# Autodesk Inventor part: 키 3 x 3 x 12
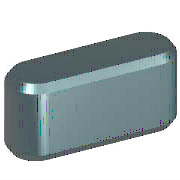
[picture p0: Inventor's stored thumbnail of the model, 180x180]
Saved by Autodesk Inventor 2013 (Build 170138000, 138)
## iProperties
Created: 2012-02
Part Number: 키 3 x 3 x 12
Material: 강철, 연강
Description: 키 및 해당 키홈
Document SubType Name: Modeling
Standard: KS B 1311
Designer: mduedu
Standards Organization: KS
Language: ko-KR
Size Designation: 3 x 3 x 12
Categories: <MemberInstance><Categories><Category DisplayName="샤프트 부품" InternalName="7f7aeb1f-a693-4053-b835-cee3144e0d98" Mnemonic="SHFT"><Category DisplayName="키" Interna
Density: 7.86 g/cm^3
Mass: 0.790122 g
Surface Area: 1.42216 cm^2
Volume: 0.100524 cm^3
IsCustomPart: 1
Author: mduedu
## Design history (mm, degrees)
workplane "Work Plane1"
workplane "Work Plane2"
sketch "스케치1"
  geometry: L1 (1.5, 1.5)-(10.5, 1.5); L2 (10.5, -1.5)-(1.5, -1.5); L3 (0, 9.4)-(0, -7.4) reference; L4 (-5, 0)-(30, 0) reference; L5 (12, 0)-(12, 7); A1 r 1.5 centre (1.5, 0) between (1.5, 1.5) and (1.5, -1.5); A2 r 1.5 centre (10.5, 0) between (10.5, -1.5) and (10.5, 1.5)
  constraints: 6 end point, 5 point on circle, 4 tangent, 3 point on line, 2 centre point, 1 horizontal, 1 parallel, 1 perpendicular
  dimensions: "d0" = 1.5 radius of A1 (= 0.5 x PB); "d13" = 1.5 radius of A2 (= 0.5 x PB); "d14" = 12 distance between parallel lines of L5 L3 (= NLG)
extrude "본체1" new body sketch "스케치1" taper "d3" = 0 deg; stored distance "d4" = 10
workplane "Work Plane3"
body "Solid1"
chamfer "모따기1" distance "d8" = 0.25 (= PHH); stored, may be unused: second distance "d9" = 0.25 (= PHH), angle "d15" = 45 deg
other parameters: "d1" = -1.8 (= -PNT), "d2" = 1.2 (= PH - PNT), "NLG" = 12 [user parameter; used in 3 equation terms], "PB" = 3 [user parameter; used in 2 equation terms], "PNT" = 1.8 [user parameter; used in 2 equation terms], "PH" = 3 [user parameter; used in 1 equation term], "PHH" = 0.25 [user parameter; used in 2 equation terms], "d10" = 0, "d16" = 0, "d17" = 0, "d18" = 0, "WDMIN" = 8 [user parameter], "PLB2" = 12 (= NLG) [user parameter], "PLB1" = 12 (= NLG) [user parameter], "RR" = 0.08 [user parameter], "PUEB" = 1.4 [user parameter]
